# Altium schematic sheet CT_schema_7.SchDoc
size 368 x 245 mm
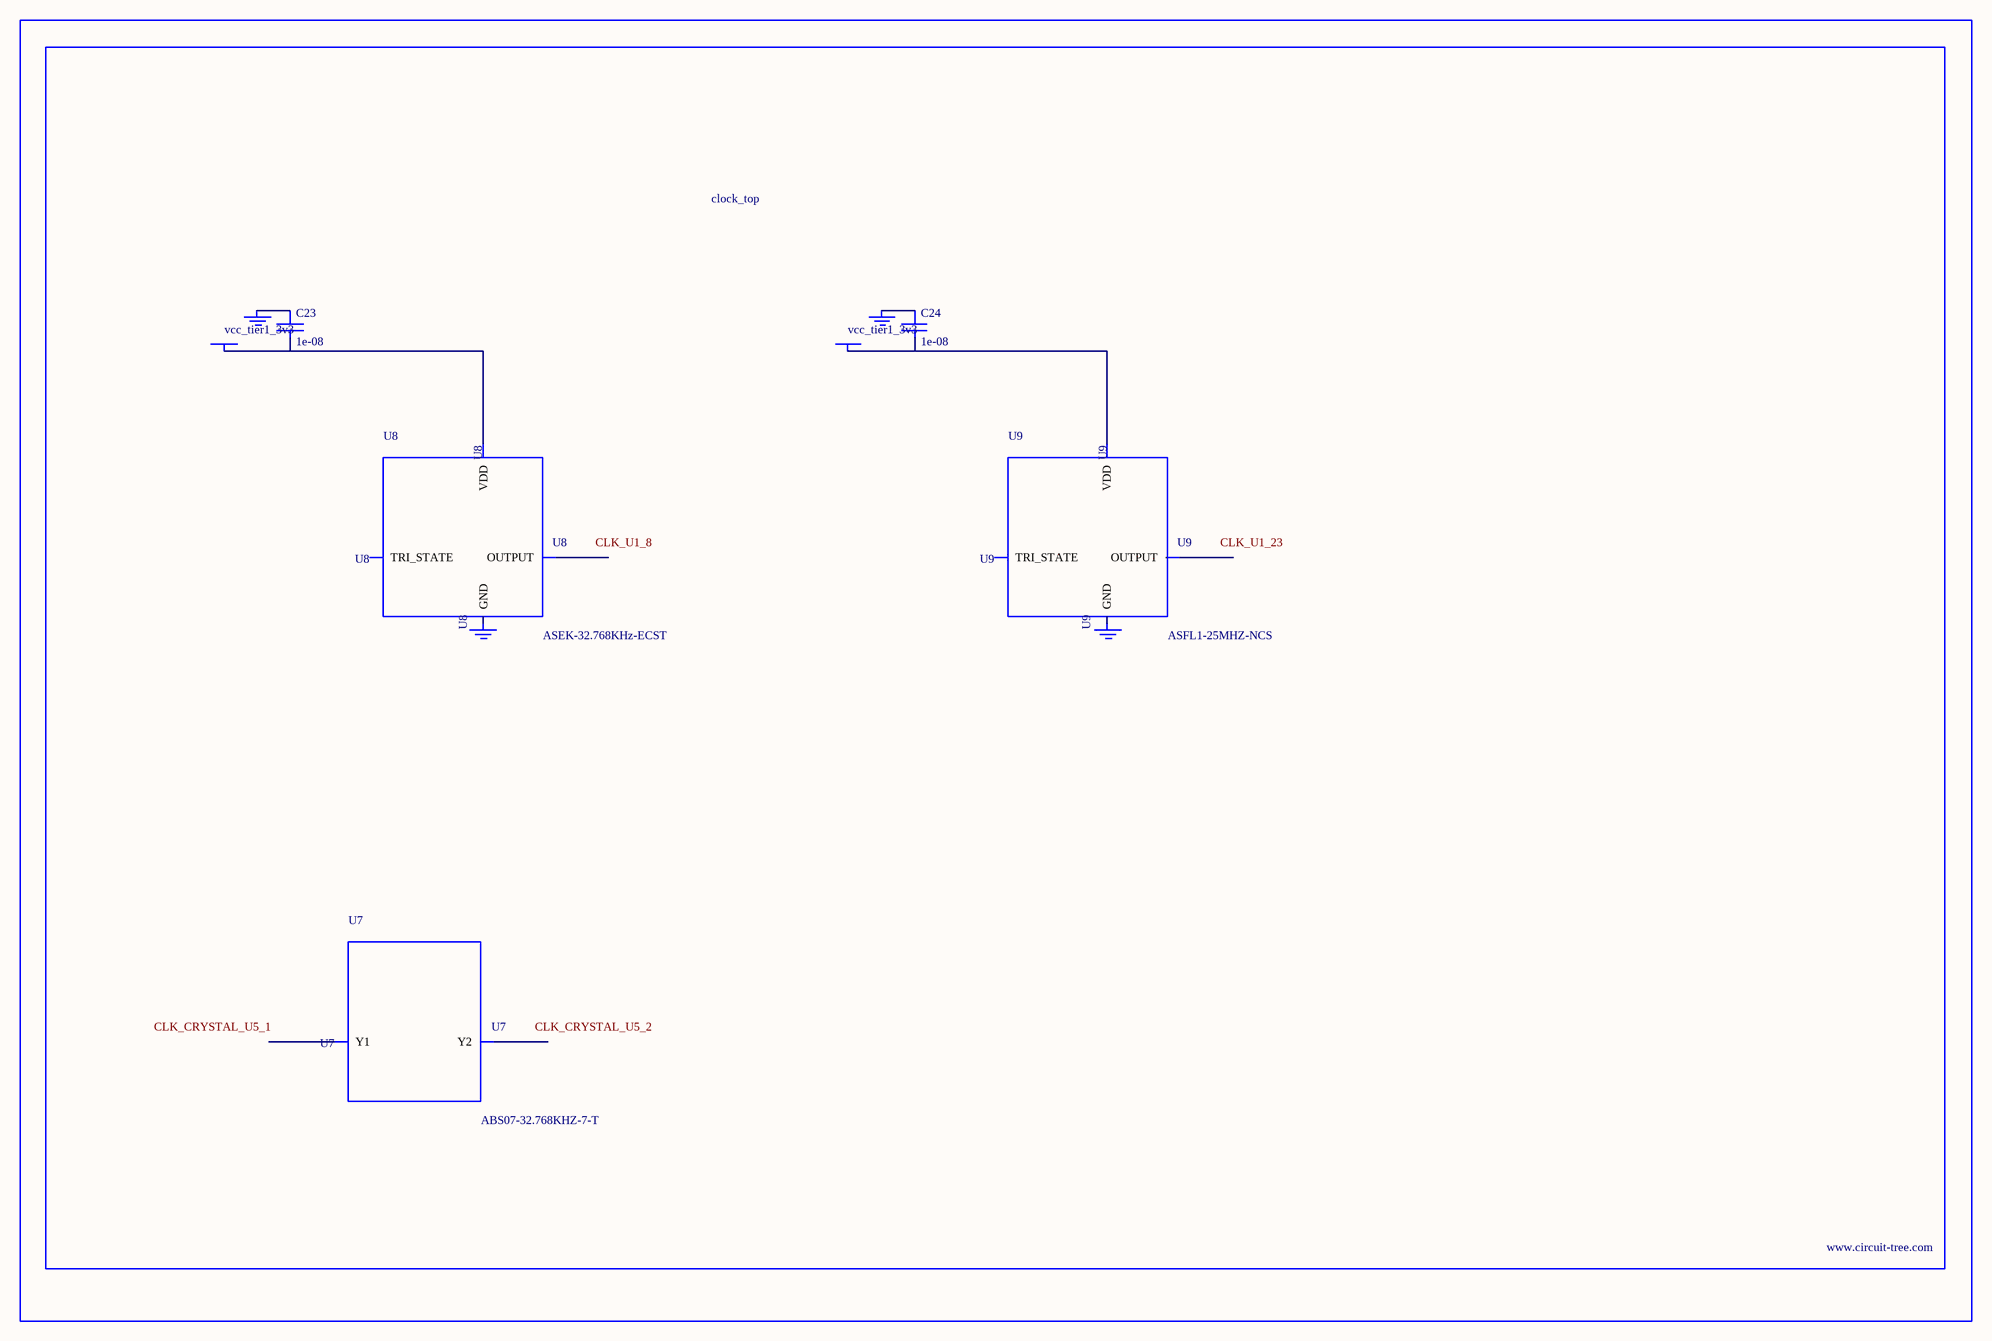
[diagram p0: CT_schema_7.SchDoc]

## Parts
BORDER6  (no value)
C23  1e-08  [C0402]
C24  1e-08  [C0402]
GND_INSTANCE_6_0  (no value)
GND_INSTANCE_6_1  (no value)
GND_INSTANCE_6_2  (no value)
GND_INSTANCE_6_3  (no value)
POWER_INSTANCE_6_0  vcc_tier1_3v3
POWER_INSTANCE_6_1  vcc_tier1_3v3
U7  ABS07-32.768KHZ-7-T  [ABS07-32.768KHZ-7-T]
U8  ASEK-32.768KHz-ECST  [ASEK]
U9  ASFL1-25MHZ-NCS  [ASFL1]

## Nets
NetC23_1: C23.1 GND_INSTANCE_6_0.0(GND)
NetC23_2: C23.2 POWER_INSTANCE_6_0.0(PWR) U8.4(VDD)
NetC24_1: C24.1 GND_INSTANCE_6_2.0(GND)
NetC24_2: C24.2 POWER_INSTANCE_6_1.0(PWR) U9.4(VDD)

Not connected (* = marked no-connect by the designer): GND_INSTANCE_6_1 0(GND); GND_INSTANCE_6_3 0(GND); U7 1(Y1) 2(Y2); U8 1(TRI_STATE) 2(GND) 3(OUTPUT); U9 1(TRI_STATE) 2(GND) 3(OUTPUT)

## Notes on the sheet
- Labels drawn without touching a wire or pin: CLK_CRYSTAL_U5_1, CLK_CRYSTAL_U5_2, CLK_U1_8, CLK_U1_23

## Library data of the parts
BORDER6 = BORDER_PAGE6
C23 C24 = C0402C103K3RAC
GND_INSTANCE_6_0-GND_INSTANCE_6_3 = GND
POWER_INSTANCE_6_0 POWER_INSTANCE_6_1 = PWR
